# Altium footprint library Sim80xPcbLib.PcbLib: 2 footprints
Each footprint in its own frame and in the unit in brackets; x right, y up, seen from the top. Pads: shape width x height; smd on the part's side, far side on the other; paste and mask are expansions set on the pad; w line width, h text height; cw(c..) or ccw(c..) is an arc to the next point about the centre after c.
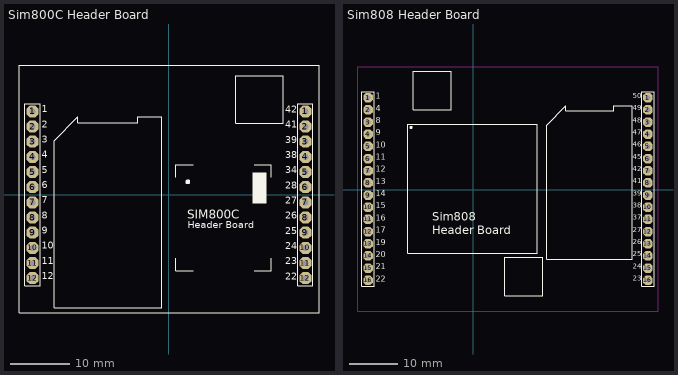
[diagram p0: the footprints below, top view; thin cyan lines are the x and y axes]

## Sim800C Header Board [mm] "Sim800C Header Board - Shop.RoboticNGO.com"
height 10
pads (24):
  oct 2x2 hole 1: 1(-22.85,13.97) 1(22.85,13.97) 2(-22.85,11.43) 2(22.85,11.43) 3(-22.85,8.89) 3(22.85,8.89) 4(-22.85,6.35) 4(22.85,6.35) 5(-22.85,3.81) 5(22.85,3.81) 6(-22.85,1.27) 6(22.85,1.27) 7(-22.85,-1.27) 7(22.85,-1.27) 8(-22.85,-3.81) 8(22.85,-3.81) 9(-22.85,-6.35) 9(22.85,-6.35) 10(-22.85,-8.89) 10(22.85,-8.89) 11(-22.85,-11.43) 11(22.85,-11.43) 12(-22.85,-13.97) 12(22.85,-13.97)
Top Overlay:
  circle w0.4: c3.15,2.17 r0.2
  rectangle: 13.95,-1.43 16.3,3.77
  lines w0.1: -25.125,-19.732 -25.125,21.671 25.127,21.657 25.127,-19.732 -25.125,-19.732
  lines w0.15: -19.25,-18.93 -19.25,9.07 -15.25,13.07 -15.25,12.07 -5.25,12.07 -5.25,13.07 -1.25,13.07 -1.25,-18.93 -19.25,-18.93 ; 11.15,11.97 11.15,19.97 19.15,19.97 19.15,11.97 11.15,11.97
  lines w0.2: 1.15,-10.63 1.15,-12.73 4.05,-12.73 ; 1.15,2.97 1.15,5.07 4.05,5.07 ; 14.25,-12.73 17.15,-12.73 17.15,-10.63 ; 14.25,5.07 17.15,5.07 17.15,2.97 ; -24.12,-15.24 -21.58,-15.24 -21.58,13.335 -21.58,15.24 -24.12,15.24 -24.12,-15.24 ; 21.58,-15.24 24.12,-15.24 24.12,13.335 24.12,15.24 21.58,15.24 21.58,-15.24
  text "Header Board" at 3.175,-6.005 h2
  text "1" at -21.325,13.37 h2
  text "2" at -21.325,10.83 h2
  text "3" at -21.325,8.29 h2
  text "4" at -21.325,5.75 h2
  text "5" at -21.325,3.21 h2
  text "6" at -21.325,0.67 h2
  text "7" at -21.325,-1.87 h2
  text "8" at -21.325,-4.41 h2
  text "9" at -21.325,-6.95 h2
  text "10" at -21.325,-9.49 h2
  text "11" at -21.325,-12.03 h2
  text "12" at -21.325,-14.57 h2
  text "42" at 19.475,13.32 h2
  text "41" at 19.475,10.78 h2
  text "39" at 19.475,8.24 h2
  text "38" at 19.475,5.7 h2
  text "34" at 19.475,3.16 h2
  text "28" at 19.475,0.62 h2
  text "27" at 19.475,-1.92 h2
  text "26" at 19.475,-4.46 h2
  text "25" at 19.475,-7 h2
  text "24" at 19.475,-9.54 h2
  text "23" at 19.475,-12.08 h2
  text "22" at 19.475,-14.62 h2
  text "SIM800C" at 3.075,-4.48 h2.5

## Sim808 Header Board [mm] "Sim808 Header Board - Shop.RoboticNGO.com"
height 10
pads (32):
  oct 2x2 hole 1: 1(-21.975,19.2) 1(36.425,19.2) 2(-21.975,16.66) 2(36.425,16.66) 3(-21.975,14.12) 3(36.425,14.12) 4(-21.975,11.58) 4(36.425,11.58) 5(-21.975,9.04) 5(36.425,9.04) 6(-21.975,6.5) 6(36.425,6.5) 7(-21.975,3.96) 7(36.425,3.96) 8(-21.975,1.42) 8(36.425,1.42) 9(-21.975,-1.12) 9(36.425,-1.12) 10(-21.975,-3.66) 10(36.425,-3.66) 11(-21.975,-6.2) 11(36.425,-6.2) 12(-21.975,-8.74) 12(36.425,-8.74) 13(-21.975,-11.28) 13(36.425,-11.28) 14(-21.975,-13.82) 14(36.425,-13.82) 15(-21.975,-16.36) 15(36.425,-16.36) 16(-21.975,-18.9) 16(36.425,-18.9)
Top Overlay:
  circle w0.4: c-13,13 r0.141
  lines w0.15: -13.7,-13.3 -13.7,13.7 13.3,13.7 13.3,-13.3 -13.7,-13.3 ; -12.575,16.7 -12.575,24.7 -4.575,24.7 -4.575,16.7 -12.575,16.7 ; 6.525,-22.1 6.525,-14.1 14.525,-14.1 14.525,-22.1 6.525,-22.1 ; 15.325,-14.5 15.325,13.5 19.325,17.5 19.325,16.5 29.325,16.5 29.325,17.5 33.15,17.5 33.15,-14.5 15.325,-14.5
  lines w0.2: -23.245,-20.17 -20.705,-20.17 -20.705,18.565 -20.705,20.47 -23.245,20.47 -23.245,-20.17 ; 35.155,-20.17 37.695,-20.17 37.695,18.565 37.695,20.47 35.155,20.47 35.155,-20.17
  text "Header Board" at -8.555,-9.891 h3
  text "1" at -20.35,18.525 h2.1
  text "4" at -20.35,15.985 h2.1
  text "8" at -20.35,13.445 h2.1
  text "22" at -20.35,-19.575 h2.1
  text "21" at -20.35,-17.035 h2.1
  text "20" at -20.35,-14.495 h2.1
  text "19" at -20.35,-11.955 h2.1
  text "17" at -20.35,-9.415 h2.1
  text "16" at -20.35,-6.875 h2.1
  text "15" at -20.35,-4.335 h2.1
  text "14" at -20.35,-1.795 h2.1
  text "13" at -20.35,0.745 h2.1
  text "12" at -20.35,3.285 h2.1
  text "11" at -20.35,5.825 h2.1
  text "10" at -20.35,8.365 h2.1
  text "9" at -20.35,10.905 h2.1
  text "50" at 33.3,18.675 h1.8
  text "49" at 33.3,16.135 h1.8
  text "48" at 33.3,13.595 h1.8
  text "47" at 33.3,11.055 h1.8
  text "46" at 33.3,8.515 h1.8
  text "45" at 33.3,5.975 h1.8
  text "42" at 33.3,3.435 h1.8
  text "41" at 33.3,0.895 h1.8
  text "39" at 33.3,-1.645 h1.8
  text "38" at 33.3,-4.185 h1.8
  text "37" at 33.3,-6.725 h1.8
  text "27" at 33.3,-9.265 h1.8
  text "26" at 33.3,-11.805 h1.8
  text "25" at 33.3,-14.345 h1.8
  text "24" at 33.3,-16.885 h1.8
  text "23" at 33.3,-19.425 h1.8
  text "Sim808" at -8.555,-7.116 h3
Keep-Out Layer:
  lines w0.2: -24.075,-25.4 38.525,-25.4 38.525,25.7 -24.075,25.7 -24.075,-25.4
